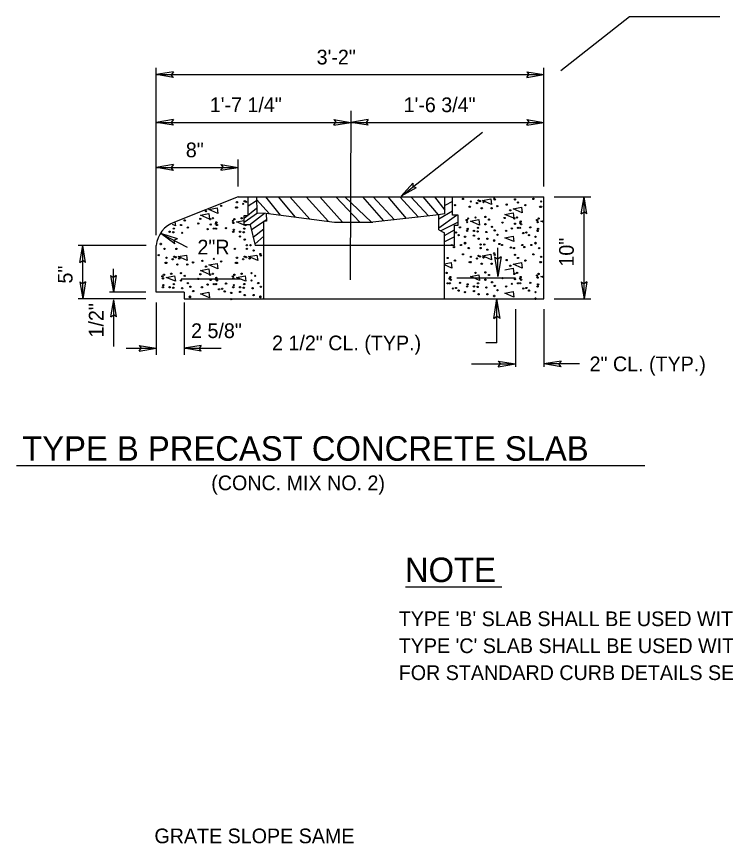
# Model space of a CAD drawing. Extents: x 4.74 to 11.91, y -5.26 to 4.54.
# Drawn here: x 4.78 to 7.673, y 1.136 to 4.512 of the extents above; entities that cross this region are included whole.
import ezdxf

# ---------------------------------------------------------------- set-up
doc = ezdxf.new("R2010")
doc.units = 0
for name, color, linetype in [('DETL-DIMS', 7, 'Continuous'), ('DETL-LINE', 7, 'Continuous'), ('DETL-NOTE', 7, 'Continuous'), ('DETL-PATT', 7, 'Continuous'), ('DETL-TITL', 7, 'Continuous')]:
    doc.layers.add(name, color=color, linetype=linetype)

msp = doc.modelspace()

# ---------------------------------------------------------------- linework, layer by layer
at = {"layer": 'DETL-DIMS'}
for p, q in [((7.0006, 4.2914), (7.2807, 4.5118)), ((7.2807, 4.5117), (7.65, 4.5117)), ((5.3505, 3.6191), (5.3505, 4.302)), ((6.9318, 3.8175), (6.9318, 4.302)), ((5.4205, 4.286), (5.3505, 4.2745)), ((5.4204, 4.2627), (5.3505, 4.2745)), ((5.3505, 4.2745), (6.9318, 4.2745)), ((5.4205, 4.286), (5.4117, 4.2744)), ((5.4204, 4.2627), (5.4117, 4.2744)), ((6.8617, 4.263), (6.8705, 4.2746)), ((6.8617, 4.263), (6.9318, 4.2745)), ((6.8618, 4.2863), (6.9318, 4.2745)), ((6.8618, 4.2863), (6.8705, 4.2746)), ((6.1434, 3.4374), (6.1449, 4.1274)), ((5.4205, 4.0913), (5.3505, 4.0798)), ((5.4205, 4.0913), (5.4117, 4.0797)), ((6.0749, 4.0916), (6.1448, 4.0798)), ((6.0749, 4.0916), (6.0836, 4.0799)), ((6.2149, 4.0913), (6.1448, 4.0798)), ((6.2149, 4.0913), (6.2061, 4.0797)), ((6.8618, 4.0916), (6.9318, 4.0798)), ((6.8618, 4.0916), (6.8705, 4.0799)), ((5.4204, 4.068), (5.3505, 4.0798)), ((5.3505, 4.0798), (6.1448, 4.0798)), ((5.4204, 4.068), (5.4117, 4.0797)), ((6.0748, 4.0683), (6.0836, 4.0799)), ((6.0748, 4.0683), (6.1448, 4.0798)), ((6.2148, 4.068), (6.1448, 4.0798)), ((6.1448, 4.0798), (6.9318, 4.0798)), ((6.2148, 4.068), (6.2061, 4.0797)), ((6.8617, 4.0683), (6.8705, 4.0799)), ((6.8617, 4.0683), (6.9318, 4.0798)), ((6.3491, 3.7789), (6.6809, 4.0399)), ((5.6842, 3.8175), (5.6842, 3.9288)), ((5.4205, 3.9071), (5.3505, 3.8956)), ((5.4204, 3.8838), (5.3505, 3.8956)), ((5.3505, 3.8956), (5.6842, 3.8956)), ((5.4205, 3.9071), (5.4117, 3.8955)), ((5.4204, 3.8838), (5.4117, 3.8955)), ((5.6142, 3.8841), (5.623, 3.8958)), ((5.6142, 3.8841), (5.6842, 3.8956)), ((5.6143, 3.9075), (5.6842, 3.8956)), ((5.6143, 3.9075), (5.623, 3.8958)), ((6.3969, 3.8314), (6.3491, 3.7789)), ((6.3969, 3.8314), (6.3972, 3.8168)), ((6.4113, 3.813), (6.3972, 3.8168)), ((6.4113, 3.813), (6.3491, 3.7789)), ((6.9734, 3.7758), (7.1231, 3.7758)), ((7.0837, 3.7058), (7.0956, 3.7758)), ((7.1071, 3.7057), (7.0956, 3.7758)), ((7.0956, 3.3589), (7.0956, 3.7758)), ((7.0837, 3.7058), (7.0955, 3.7145)), ((7.1071, 3.7057), (7.0955, 3.7145)), ((5.3689, 3.6263), (5.4768, 3.5705)), ((5.4257, 3.5838), (5.3689, 3.6263)), ((5.4365, 3.6045), (5.3689, 3.6263)), ((5.4365, 3.6045), (5.4233, 3.5982)), ((5.4257, 3.5838), (5.4233, 3.5982)), ((5.3088, 3.5775), (5.0313, 3.5775)), ((5.0389, 3.5075), (5.0507, 3.5775)), ((5.0502, 3.3589), (5.0507, 3.5775)), ((5.0622, 3.5074), (5.0507, 3.5775)), ((6.7441, 3.4511), (6.7441, 3.5682)), ((5.0389, 3.5075), (5.0506, 3.5162)), ((5.0622, 3.5074), (5.0506, 3.5162)), ((6.7307, 3.5311), (6.7441, 3.4511)), ((6.7307, 3.5311), (6.7441, 3.5211)), ((6.7574, 3.5311), (6.7441, 3.4511)), ((6.7574, 3.5311), (6.7441, 3.5211)), ((5.1753, 3.385), (5.1755, 3.4817)), ((5.1638, 3.4551), (5.1753, 3.385)), ((5.1638, 3.4551), (5.1754, 3.4463)), ((5.1871, 3.455), (5.1753, 3.385)), ((5.1871, 3.455), (5.1754, 3.4463)), ((5.0387, 3.4289), (5.0502, 3.3589)), ((5.0387, 3.4289), (5.0503, 3.4201)), ((5.062, 3.4288), (5.0502, 3.3589)), ((5.062, 3.4288), (5.0503, 3.4201)), ((7.0841, 3.4289), (7.0956, 3.3589)), ((7.0841, 3.4289), (7.0957, 3.4201)), ((7.1074, 3.4288), (7.0956, 3.3589)), ((7.1074, 3.4288), (7.0957, 3.4201)), ((5.3084, 3.3863), (5.1597, 3.3863)), ((5.3084, 3.3589), (5.0313, 3.3589)), ((5.1652, 3.2859), (5.1771, 3.3558)), ((5.1767, 3.1651), (5.1771, 3.3558)), ((5.1886, 3.2858), (5.1771, 3.3558)), ((5.35, 3.3446), (5.35, 3.1301)), ((5.464, 3.3446), (5.464, 3.1301)), ((6.727, 3.2789), (6.7403, 3.3589)), ((6.7536, 3.2789), (6.7403, 3.3589)), ((6.7403, 3.1793), (6.7403, 3.3589)), ((6.9734, 3.3589), (7.1231, 3.3589)), ((6.8157, 3.3172), (6.8157, 3.0814)), ((6.9318, 3.3172), (6.9318, 3.0814)), ((5.1652, 3.2859), (5.177, 3.2946)), ((5.1886, 3.2858), (5.177, 3.2946)), ((6.727, 3.2789), (6.7403, 3.2889)), ((6.7536, 3.2789), (6.7403, 3.2889)), ((6.7403, 3.1793), (6.6944, 3.1793)), ((5.2271, 3.158), (5.35, 3.1577)), ((5.28, 3.1462), (5.2888, 3.1578)), ((5.28, 3.1462), (5.35, 3.1577)), ((5.2801, 3.1695), (5.35, 3.1577)), ((5.2801, 3.1695), (5.2888, 3.1578)), ((5.534, 3.1692), (5.464, 3.1577)), ((5.5339, 3.1458), (5.464, 3.1577)), ((5.464, 3.1577), (5.6151, 3.1573)), ((5.534, 3.1692), (5.5252, 3.1575)), ((5.5339, 3.1458), (5.5252, 3.1575)), ((6.6366, 3.0938), (6.8157, 3.0938)), ((6.7457, 3.1055), (6.8157, 3.0938)), ((6.7457, 3.1055), (6.7545, 3.0938)), ((6.7457, 3.0821), (6.8157, 3.0938)), ((6.7457, 3.0821), (6.7545, 3.0938)), ((7.0017, 3.1055), (6.9318, 3.0938)), ((7.0017, 3.0821), (6.9318, 3.0938)), ((7.0767, 3.0938), (6.9318, 3.0938)), ((7.0017, 3.1055), (6.993, 3.0938)), ((7.0017, 3.0821), (6.993, 3.0938))]:
    msp.add_line(p, q, dxfattribs=at)
at = {"layer": 'DETL-LINE'}
for p, q in [((5.6842, 3.7758), (5.4244, 3.6723)), ((5.6842, 3.7758), (6.9318, 3.7758)), ((5.7252, 3.6991), (5.7254, 3.7757)), ((5.7594, 3.7758), (5.7601, 3.711)), ((6.5283, 3.7058), (6.5283, 3.7758)), ((6.5592, 3.701), (6.5594, 3.7758)), ((6.9318, 3.3589), (6.9318, 3.7758)), ((5.7086, 3.6611), (5.7087, 3.6991)), ((5.7087, 3.6991), (5.7252, 3.6991)), ((5.7601, 3.7103), (5.7975, 3.7085)), ((5.7975, 3.7085), (6.0776, 3.6718)), ((5.7985, 3.7083), (5.8007, 3.676)), ((6.5029, 3.7024), (6.2335, 3.6725)), ((6.5283, 3.7058), (6.5, 3.7019)), ((6.5037, 3.6408), (6.5037, 3.7024)), ((6.582, 3.701), (6.5592, 3.701)), ((6.5819, 3.6607), (6.582, 3.701)), ((5.733, 3.6611), (5.7086, 3.6611)), ((5.733, 3.6611), (5.7545, 3.5767)), ((5.7891, 3.3589), (5.7898, 3.676)), ((5.8007, 3.676), (5.7898, 3.676)), ((6.0776, 3.6718), (6.2335, 3.6725)), ((6.5665, 3.5767), (6.5667, 3.6607)), ((6.5667, 3.6607), (6.5819, 3.6607)), ((6.5037, 3.6408), (6.5259, 3.6287)), ((6.5259, 3.3589), (6.5259, 3.6287)), ((5.35, 3.3863), (5.3505, 3.5775)), ((6.5665, 3.5767), (5.7545, 3.5767)), ((6.5771, 3.4445), (6.8165, 3.4445)), ((5.4523, 3.441), (5.6963, 3.4405)), ((5.464, 3.386), (5.35, 3.3863)), ((5.464, 3.386), (5.464, 3.3589)), ((5.464, 3.3589), (6.9318, 3.3589))]:
    msp.add_line(p, q, dxfattribs=at)
msp.add_arc((5.4617, 3.5669), 0.1117, 109.5105, 174.5967, dxfattribs=at)
at = {"layer": 'DETL-NOTE'}
msp.add_line((6.3667, 2.1835), (6.7597, 2.1835), dxfattribs=at)
at = {"layer": 'DETL-PATT'}
for p, q in [((5.7253, 3.7394), (5.7596, 3.7602)), ((5.7595, 3.7654), (5.8125, 3.7065)), ((5.7966, 3.7758), (5.8563, 3.7007)), ((5.9185, 3.6926), (5.8487, 3.7758)), ((5.9772, 3.6849), (5.8957, 3.7758)), ((5.9617, 3.7758), (6.0525, 3.6751)), ((6.1099, 3.6719), (6.0173, 3.7758)), ((6.0831, 3.7758), (6.1803, 3.6723)), ((6.2285, 3.6724), (6.1195, 3.7758)), ((6.1919, 3.7758), (6.2777, 3.6774)), ((6.3218, 3.6822), (6.2352, 3.7758)), ((6.295, 3.7758), (6.3702, 3.6876)), ((6.4204, 3.6932), (6.344, 3.7758)), ((6.3893, 3.7758), (6.4605, 3.6977)), ((6.4373, 3.7758), (6.5004, 3.7021)), ((6.486, 3.7758), (6.5283, 3.7215)), ((6.5593, 3.7569), (6.5283, 3.7409)), ((6.6809, 3.7611), (6.7153, 3.7678)), ((6.7183, 3.745), (6.6809, 3.7611)), ((6.7153, 3.7678), (6.7183, 3.745)), ((5.6021, 3.7078), (5.5647, 3.7239)), ((5.5991, 3.7306), (5.6021, 3.7078)), ((5.7087, 3.6891), (5.7599, 3.7296)), ((6.5037, 3.6862), (6.5592, 3.7188)), ((6.806, 3.7271), (6.8405, 3.7339)), ((6.8435, 3.7111), (6.806, 3.7271)), ((6.8405, 3.7339), (6.8435, 3.7111)), ((5.5307, 3.7011), (5.5652, 3.7078)), ((5.5682, 3.685), (5.5307, 3.7011)), ((5.5652, 3.7078), (5.5682, 3.685)), ((5.7087, 3.6722), (5.7636, 3.7101)), ((5.7305, 3.6611), (5.7923, 3.7087)), ((5.7382, 3.641), (5.8003, 3.6832)), ((6.5037, 3.6498), (6.5753, 3.701)), ((6.6321, 3.6767), (6.6666, 3.6835)), ((6.6666, 3.6835), (6.6696, 3.6607)), ((6.7721, 3.7043), (6.8065, 3.7111)), ((6.8095, 3.6883), (6.7721, 3.7043)), ((6.8065, 3.7111), (6.8095, 3.6883)), ((6.582, 3.6719), (6.5113, 3.6367)), ((6.6696, 3.6607), (6.6321, 3.6767)), ((5.7457, 3.6113), (5.7897, 3.6451)), ((5.7531, 3.5822), (5.7897, 3.6153)), ((6.5259, 3.6184), (6.5666, 3.6411)), ((6.5665, 3.6122), (6.5259, 3.5917)), ((6.7721, 3.6089), (6.8065, 3.6157)), ((6.8065, 3.6157), (6.8095, 3.5929)), ((6.8095, 3.5929), (6.7721, 3.6089)), ((5.4395, 3.5315), (5.474, 3.5382)), ((5.477, 3.5154), (5.4395, 3.5315)), ((5.474, 3.5382), (5.477, 3.5154)), ((5.7268, 3.5315), (5.7612, 3.5382)), ((5.7642, 3.5154), (5.7268, 3.5315)), ((5.7612, 3.5382), (5.7642, 3.5154)), ((6.6809, 3.5347), (6.7153, 3.5415)), ((6.7183, 3.5187), (6.6809, 3.5347)), ((6.7153, 3.5415), (6.7183, 3.5187)), ((5.5307, 3.4747), (5.5652, 3.4815)), ((5.5647, 3.4975), (5.5991, 3.5042)), ((5.6021, 3.4815), (5.5647, 3.4975)), ((5.5652, 3.4815), (5.5682, 3.4587)), ((5.5991, 3.5042), (5.6021, 3.4815)), ((6.5532, 3.5075), (6.5562, 3.4847)), ((6.7721, 3.478), (6.8065, 3.4847)), ((6.806, 3.5008), (6.8405, 3.5075)), ((6.8435, 3.4847), (6.806, 3.5008)), ((6.8065, 3.4847), (6.8095, 3.4619)), ((6.8405, 3.5075), (6.8435, 3.4847)), ((5.3908, 3.4471), (5.4253, 3.4539)), ((5.4283, 3.4311), (5.3908, 3.4471)), ((5.4253, 3.4539), (5.4283, 3.4311)), ((5.5682, 3.4587), (5.5307, 3.4747)), ((5.678, 3.4471), (5.7125, 3.4539)), ((5.7155, 3.4311), (5.678, 3.4471)), ((5.7125, 3.4539), (5.7155, 3.4311)), ((6.6321, 3.4504), (6.6666, 3.4571)), ((6.6696, 3.4343), (6.6321, 3.4504)), ((6.6666, 3.4571), (6.6696, 3.4343)), ((5.5307, 3.3793), (5.5652, 3.386)), ((5.5682, 3.3632), (5.5307, 3.3793)), ((5.5652, 3.386), (5.5682, 3.3632)), ((6.7721, 3.3825), (6.8065, 3.3893)), ((6.8095, 3.3665), (6.7721, 3.3825)), ((6.8065, 3.3893), (6.8095, 3.3665))]:
    msp.add_line(p, q, dxfattribs=at)
for points in [[(5.5647, 3.7239), (5.5991, 3.7306)], [(5.4283, 3.6575), (5.4167, 3.6624)], [(5.4262, 3.673), (5.4283, 3.6575)], [(5.678, 3.6735), (5.7086, 3.6795)], [(5.7155, 3.6575), (5.678, 3.6735)], [(5.715, 3.6611), (5.7155, 3.6575)], [(6.9194, 3.6767), (6.9318, 3.6792)], [(6.9318, 3.6714), (6.9194, 3.6767)], [(6.5562, 3.4847), (6.5263, 3.4976)], [(6.5263, 3.5023), (6.5532, 3.5075)], [(6.9194, 3.4504), (6.9318, 3.4528)], [(6.9318, 3.4451), (6.9194, 3.4504)]]:
    msp.add_lwpolyline(points, dxfattribs=at)
for centre in [(5.6795, 3.7535), (5.705, 3.7471), (5.7111, 3.7578), (5.717, 3.7552), (6.6018, 3.7673), (6.6336, 3.7567), (6.6591, 3.7504), (6.6652, 3.761), (6.6711, 3.7585), (6.6853, 3.754), (6.7291, 3.7715), (6.7312, 3.7652), (6.8139, 3.7652), (6.8266, 3.7525), (6.8891, 3.7673), (6.9209, 3.7567), (5.5535, 3.7174), (5.615, 3.7386), (5.6753, 3.7323), (5.6795, 3.7323), (6.569, 3.7419), (6.6294, 3.7355), (6.6782, 3.7292), (6.7185, 3.7292), (6.7418, 3.7376), (6.78, 3.744), (6.7948, 3.7207), (6.8563, 3.7419), (6.9167, 3.7355), (6.9209, 3.7355), (5.4665, 3.6797), (5.5301, 3.6861), (5.5704, 3.684), (5.581, 3.6883), (5.6626, 3.6776), (5.669, 3.684), (5.6986, 3.6883), (6.6167, 3.6809), (6.623, 3.6872), (6.6527, 3.6915), (6.693, 3.6936), (6.7079, 3.683), (6.7715, 3.6894), (6.8117, 3.6872), (6.8224, 3.6915), (6.9039, 3.6809), (6.9103, 3.6872), (5.422, 3.6458), (5.4517, 3.6607), (5.4792, 3.6501), (5.5217, 3.667), (5.5598, 3.6437), (5.5725, 3.6628), (5.5852, 3.6458), (5.5938, 3.6649), (5.5938, 3.6458), (5.5959, 3.6713), (5.598, 3.6607), (5.635, 3.648), (5.6647, 3.6692), (5.7092, 3.6458), (6.5891, 3.6512), (6.6188, 3.6724), (6.6209, 3.6448), (6.6633, 3.6491), (6.693, 3.6639), (6.7206, 3.6533), (6.763, 3.6703), (6.8012, 3.647), (6.8139, 3.666), (6.8266, 3.6491), (6.8351, 3.6682), (6.8351, 3.6491), (6.8372, 3.6745), (6.8393, 3.6639), (6.8764, 3.6512), (6.906, 3.6724), (6.9082, 3.6448), (5.405, 3.6331), (5.4199, 3.631), (5.4559, 3.6289), (5.6647, 3.6331), (5.6668, 3.6416), (5.6923, 3.6331), (5.6923, 3.614), (5.7071, 3.631), (6.5733, 3.63), (6.5839, 3.6194), (6.6103, 3.613), (6.6188, 3.6364), (6.6464, 3.6364), (6.6464, 3.6173), (6.6612, 3.6342), (6.6972, 3.6321), (6.7312, 3.6385), (6.7425, 3.6209), (6.7778, 3.6364), (6.8478, 3.6279), (6.8605, 3.63), (6.8711, 3.6194), (6.8976, 3.613), (6.906, 3.6364), (5.369, 3.5843), (5.369, 3.5822), (5.7114, 3.6013), (5.7198, 3.578), (5.7347, 3.578), (6.5563, 3.5791), (6.5934, 3.5791), (6.6103, 3.5876), (6.6103, 3.5855), (6.6655, 3.6045), (6.6739, 3.5812), (6.6888, 3.5812), (6.7015, 3.6045), (6.7291, 3.5982), (6.7291, 3.5961), (6.7502, 3.5833), (6.7609, 3.5791), (6.8436, 3.5791), (6.8806, 3.5791), (6.8976, 3.5876), (6.8976, 3.5855), (5.3838, 3.5631), (5.4326, 3.5631), (5.6711, 3.5631), (5.7198, 3.5631), (5.7474, 3.5568), (5.775, 3.5419), (6.5648, 3.5706), (6.6252, 3.5664), (6.6739, 3.5664), (6.7015, 3.56), (6.7291, 3.5452), (6.7969, 3.5685), (6.8096, 3.5664), (6.852, 3.5706), (6.9124, 3.5664), (5.3605, 3.5377), (5.3923, 3.5271), (5.4177, 3.5208), (5.4239, 3.5314), (5.4297, 3.5289), (5.444, 3.5243), (5.5386, 3.5144), (5.5852, 3.5228), (5.615, 3.5122), (5.6795, 3.5271), (5.705, 3.5208), (5.7111, 3.5314), (5.717, 3.5289), (5.7312, 3.5243), (5.7771, 3.5356), (6.5393, 3.5261), (6.569, 3.5155), (6.6018, 3.541), (6.6294, 3.5091), (6.6336, 3.5303), (6.6336, 3.5091), (6.6591, 3.524), (6.6652, 3.5347), (6.6711, 3.5321), (6.6853, 3.5276), (6.7312, 3.5388), (6.78, 3.5176), (6.8139, 3.5388), (6.8266, 3.5261), (6.8563, 3.5155), (6.8891, 3.541), (6.9167, 3.5091), (6.9209, 3.5303), (6.9209, 3.5091), (5.3881, 3.5059), (5.3923, 3.5059), (5.4368, 3.4995), (5.4771, 3.4995), (5.5005, 3.508), (5.5535, 3.491), (5.6753, 3.5059), (5.6795, 3.5059), (6.6782, 3.5028), (6.7185, 3.5028), (6.7948, 3.4943), (5.3753, 3.4512), (5.3775, 3.4428), (5.3817, 3.4576), (5.4114, 3.4619), (5.4517, 3.464), (5.4665, 3.4534), (5.5217, 3.4407), (5.5301, 3.4598), (5.5704, 3.4576), (5.581, 3.4619), (5.5959, 3.4449), (5.6626, 3.4512), (5.6647, 3.4428), (5.669, 3.4576), (5.6986, 3.4619), (5.7389, 3.464), (5.7538, 3.4534), (6.5351, 3.4651), (6.5478, 3.4418), (6.55, 3.4482), (6.6527, 3.4651), (6.693, 3.4672), (6.7079, 3.4566), (6.763, 3.4439), (6.8117, 3.4609), (6.8224, 3.4651), (6.8351, 3.4418), (6.8372, 3.4482), (6.9039, 3.4545), (6.906, 3.446), (6.9103, 3.4609), (5.3796, 3.4152), (5.422, 3.4195), (5.4517, 3.4343), (5.4792, 3.4237), (5.4898, 3.4089), (5.5598, 3.4173), (5.5725, 3.4364), (5.5852, 3.4195), (5.5938, 3.4385), (5.5938, 3.4195), (5.598, 3.4343), (5.635, 3.4216), (5.6668, 3.4152), (5.7092, 3.4195), (5.7389, 3.4343), (5.7665, 3.4237), (5.7771, 3.4089), (6.5393, 3.4227), (6.5478, 3.4227), (6.5521, 3.4375), (6.5891, 3.4248), (6.6188, 3.41), (6.6209, 3.4185), (6.6464, 3.41), (6.6612, 3.4079), (6.6633, 3.4227), (6.693, 3.4375), (6.7206, 3.427), (6.7312, 3.4121), (6.7778, 3.41), (6.8012, 3.4206), (6.8139, 3.4397), (6.8266, 3.4227), (6.8351, 3.4227), (6.8393, 3.4375), (6.8764, 3.4248), (6.906, 3.41), (6.9082, 3.4185), (5.3775, 3.4067), (5.405, 3.4067), (5.4199, 3.4046), (5.4559, 3.4025), (5.5012, 3.3912), (5.5365, 3.4067), (5.6065, 3.3982), (5.6192, 3.4004), (5.6298, 3.3898), (5.6562, 3.3834), (5.6647, 3.4067), (5.6923, 3.4067), (5.6923, 3.3877), (5.7071, 3.4046), (5.7114, 3.3749), (5.7432, 3.4025), (5.7474, 3.3749), (6.5605, 3.4015), (6.5733, 3.4036), (6.5839, 3.393), (6.6103, 3.3867), (6.6464, 3.3909), (6.6655, 3.3782), (6.6972, 3.4057), (6.7015, 3.3782), (6.7425, 3.3945), (6.8478, 3.4015), (6.8605, 3.4036), (6.8711, 3.393), (6.8976, 3.3867), (5.4878, 3.3686), (5.4878, 3.3665), (5.6562, 3.358), (5.775, 3.3686), (5.775, 3.3665), (6.7291, 3.3718), (6.7291, 3.3697), (6.8976, 3.3612), (6.8976, 3.3591)]:
    msp.add_circle(centre, 0.00262, dxfattribs=at)
at = {"layer": 'DETL-TITL'}
msp.add_line((4.7803, 2.6787), (7.3437, 2.6787), dxfattribs=at)

# ---------------------------------------------------------------- texts
at = {"layer": 'DETL-NOTE'}
for s, height, p in [('3\'-2"', 0.06, (6.0047, 4.3162)), ('1\'-7 1/4"', 0.06, (5.5689, 4.1215)), ('1\'-6 3/4"', 0.06, (6.3595, 4.1215)), ('8"', 0.06, (5.471, 3.9373)), ('2"R', 0.06, (5.5184, 3.5405)), ('2 5/8"', 0.06, (5.4925, 3.1992)), ('2 1/2" CL. (TYP.)', 0.06, (5.8228, 3.1493)), ('2" CL. (TYP.)', 0.06, (7.1183, 3.0638)), ('(CONC. MIX NO. 2)', 0.06, (5.5747, 2.5781)), ('NOTE', 0.1, (6.3647, 2.2031)), ("TYPE 'B' SLAB SHALL BE USED WITH STD. TYPE 'B' CONC CURB", 0.06, (6.3397, 2.0232)), ("TYPE 'C' SLAB SHALL BE USED WITH STD. TYPE 'C' CONC CURB", 0.06, (6.3397, 1.9132)), ('FOR STANDARD CURB DETAILS SEE STD. MD 620.02.', 0.06, (6.3397, 1.8032)), ('GRATE SLOPE SAME', 0.06, (5.3429, 1.1369))]:
    msp.add_text(s, height=height, dxfattribs=at).set_placement(p)
for s, p in [('10"', (7.0539, 3.491)), ('5"', (5.0088, 3.4218)), ('1/2"', (5.1352, 3.2017))]:
    msp.add_text(s, height=0.06, rotation=90, dxfattribs=at).set_placement(p)
at = {"layer": 'DETL-TITL'}
msp.add_text('TYPE B PRECAST CONCRETE SLAB', height=0.1, dxfattribs=at).set_placement((4.8035, 2.6984))

doc.saveas('drawing.dxf')
